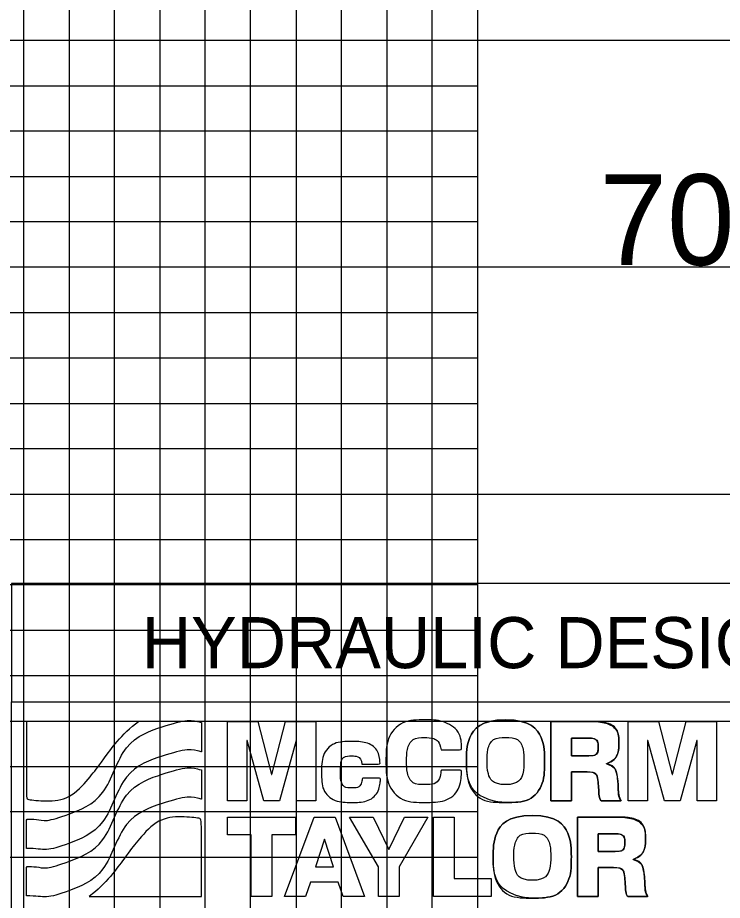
# Model space of a CAD drawing. Extents: x 1524869 to 1526553, y 501099 to 502199.
# Drawn here: x 1526435.4 to 1526513, y 501178.8 to 501276.1 of the extents above; entities that cross this region are included whole.
import ezdxf

# ---------------------------------------------------------------- set-up
doc = ezdxf.new("R2010")
doc.units = 0
for name, color, linetype in [('Exist Vertical Profile Vertical Axis Label', 7, 'Continuous'), ('Prop Grid Mask', 7, 'Continuous'), ('Prop Horizontal Alignment Curve and Spiral Data', 7, 'Continuous'), ('Sheet Layout Profile Border Port 1', 7, 'Continuous'), ('Sheet Profile Grid Major CELL', 7, 'Continuous'), ('Sheet Profile Grid Middle CELL', 7, 'Continuous'), ('Sheet Profile Grid Minor CELL', 7, 'Continuous')]:
    doc.layers.add(name, color=color, linetype=linetype)

msp = doc.modelspace()

# ---------------------------------------------------------------- linework, layer by layer
at = {"layer": 'Prop Grid Mask'}
for points in [[(1526434.749, 501200.682), (1526536.08, 501200.682), (1526536.08, 501213.727), (1526434.749, 501213.727)], [(1526434.749, 501200.682), (1526536.08, 501200.682), (1526536.08, 501148.562), (1526434.749, 501148.562)]]:
    msp.add_lwpolyline(points, close=True, dxfattribs=at)
at = {"layer": 'Prop Horizontal Alignment Curve and Spiral Data'}
for p, q in [((1526458.537, 501198.515), (1526461.888, 501198.515)), ((1526458.537, 501189.785), (1526458.537, 501198.515)), ((1526461.888, 501198.515), (1526463.392, 501192.695)), ((1526463.416, 501192.695), (1526464.92, 501198.515)), ((1526464.92, 501198.515), (1526468.27, 501198.515)), ((1526468.27, 501198.515), (1526468.27, 501189.785)), ((1526502.67, 501198.515), (1526506.021, 501198.515)), ((1526502.67, 501189.785), (1526502.67, 501198.515)), ((1526506.021, 501198.515), (1526507.524, 501192.695)), ((1526507.549, 501192.695), (1526509.052, 501198.515)), ((1526509.052, 501198.515), (1526512.403, 501198.515)), ((1526512.403, 501198.515), (1526512.403, 501189.785)), ((1526460.702, 501196.412), (1526460.677, 501196.412)), ((1526460.677, 501196.412), (1526460.677, 501189.785)), ((1526462.536, 501189.785), (1526460.702, 501196.412)), ((1526466.106, 501196.412), (1526464.272, 501189.785)), ((1526466.13, 501196.412), (1526466.106, 501196.412)), ((1526466.13, 501189.785), (1526466.13, 501196.412)), ((1526504.835, 501196.412), (1526504.81, 501196.412)), ((1526504.81, 501196.412), (1526504.81, 501189.785)), ((1526506.668, 501189.785), (1526504.835, 501196.412)), ((1526510.238, 501196.412), (1526508.404, 501189.785)), ((1526510.263, 501196.412), (1526510.238, 501196.412)), ((1526510.263, 501189.785), (1526510.263, 501196.412)), ((1526500.273, 501193.868), (1526500.273, 501193.844)), ((1526463.392, 501192.695), (1526463.416, 501192.695)), ((1526507.524, 501192.695), (1526507.549, 501192.695)), ((1526460.677, 501189.785), (1526458.537, 501189.785)), ((1526464.272, 501189.785), (1526462.536, 501189.785)), ((1526468.27, 501189.785), (1526466.13, 501189.785)), ((1526501.911, 501189.785), (1526499.662, 501189.785)), ((1526504.81, 501189.785), (1526502.67, 501189.785)), ((1526508.404, 501189.785), (1526506.668, 501189.785)), ((1526512.403, 501189.785), (1526510.263, 501189.785)), ((1526458.537, 501186.021), (1526458.537, 501187.977)), ((1526458.537, 501187.977), (1526466.02, 501187.977)), ((1526464.799, 501179.247), (1526468.064, 501187.977)), ((1526466.02, 501187.977), (1526466.02, 501186.021)), ((1526468.064, 501187.977), (1526470.374, 501187.977)), ((1526470.374, 501187.977), (1526473.639, 501179.247)), ((1526475.16, 501182.499), (1526471.981, 501187.977)), ((1526471.981, 501187.977), (1526474.561, 501187.977)), ((1526474.561, 501187.977), (1526476.297, 501184.431)), ((1526476.297, 501184.431), (1526478.034, 501187.977)), ((1526480.613, 501187.977), (1526477.435, 501182.499)), ((1526478.034, 501187.977), (1526480.613, 501187.977)), ((1526481.214, 501187.977), (1526483.488, 501187.977)), ((1526481.214, 501179.247), (1526481.214, 501187.977)), ((1526483.488, 501187.977), (1526483.488, 501181.203)), ((1526461.142, 501186.021), (1526458.537, 501186.021)), ((1526461.142, 501179.247), (1526461.142, 501186.021)), ((1526466.02, 501186.021), (1526463.416, 501186.021)), ((1526463.416, 501186.021), (1526463.416, 501179.247)), ((1526469.201, 501185.556), (1526468.21, 501182.499)), ((1526469.225, 501185.556), (1526469.201, 501185.556)), ((1526470.191, 501182.499), (1526469.225, 501185.556)), ((1526503.207, 501183.33), (1526503.207, 501183.306)), ((1526468.21, 501182.499), (1526470.191, 501182.499)), ((1526475.16, 501179.247), (1526475.16, 501182.499)), ((1526477.435, 501182.499), (1526477.435, 501179.247)), ((1526483.488, 501181.203), (1526487.56, 501181.203)), ((1526487.56, 501181.203), (1526487.56, 501179.247)), ((1526467.685, 501180.811), (1526467.134, 501179.247)), ((1526470.729, 501180.811), (1526467.685, 501180.811)), ((1526471.267, 501179.247), (1526470.729, 501180.811)), ((1526463.416, 501179.247), (1526461.142, 501179.247)), ((1526467.134, 501179.247), (1526464.799, 501179.247)), ((1526473.639, 501179.247), (1526471.267, 501179.247)), ((1526477.435, 501179.247), (1526475.16, 501179.247)), ((1526487.56, 501179.247), (1526481.214, 501179.247)), ((1526504.845, 501179.247), (1526502.596, 501179.247))]:
    msp.add_line(p, q, dxfattribs=at)
for points in [[(1526458.537, 501198.515), (1526461.888, 501198.515), (1526463.392, 501192.695), (1526463.416, 501192.695), (1526464.92, 501198.515), (1526468.27, 501198.515), (1526468.27, 501189.785), (1526466.13, 501189.785), (1526466.13, 501196.412), (1526466.106, 501196.412), (1526464.272, 501189.785), (1526462.536, 501189.785), (1526460.702, 501196.412), (1526460.677, 501196.412), (1526460.677, 501189.785), (1526458.537, 501189.785), (1526458.537, 501198.515)], [(1526498.133, 501192.964), (1526496.409, 501192.964), (1526496.409, 501189.785), (1526494.135, 501189.785), (1526494.135, 501198.515), (1526498.586, 501198.515)], [(1526502.67, 501198.515), (1526506.021, 501198.515), (1526507.524, 501192.695), (1526507.549, 501192.695), (1526509.052, 501198.515), (1526512.403, 501198.515), (1526512.403, 501189.785), (1526510.263, 501189.785), (1526510.263, 501196.412), (1526510.238, 501196.412), (1526508.404, 501189.785), (1526506.668, 501189.785), (1526504.835, 501196.412), (1526504.81, 501196.412), (1526504.81, 501189.785), (1526502.67, 501189.785), (1526502.67, 501198.515)], [(1526498.219, 501196.693), (1526496.409, 501196.693), (1526496.409, 501194.724), (1526498.317, 501194.724)], [(1526466.02, 501186.021), (1526463.416, 501186.021), (1526463.416, 501179.247), (1526461.142, 501179.247), (1526461.142, 501186.021), (1526458.537, 501186.021), (1526458.537, 501187.977), (1526466.02, 501187.977), (1526466.02, 501186.021)], [(1526468.064, 501187.977), (1526470.374, 501187.977), (1526473.639, 501179.247), (1526471.267, 501179.247), (1526470.729, 501180.811), (1526467.685, 501180.811), (1526467.134, 501179.247), (1526464.799, 501179.247), (1526468.064, 501187.977)], [(1526477.435, 501182.499), (1526477.435, 501179.247), (1526475.16, 501179.247), (1526475.16, 501182.499), (1526471.981, 501187.977), (1526474.561, 501187.977), (1526476.297, 501184.431), (1526478.034, 501187.977), (1526480.613, 501187.977), (1526477.435, 501182.499)], [(1526481.214, 501187.977), (1526483.488, 501187.977), (1526483.488, 501181.203), (1526487.56, 501181.203), (1526487.56, 501179.247), (1526481.214, 501179.247), (1526481.214, 501187.977)], [(1526501.067, 501182.426), (1526499.343, 501182.426), (1526499.343, 501179.247), (1526497.069, 501179.247), (1526497.069, 501187.977), (1526501.519, 501187.977)], [(1526501.153, 501186.155), (1526499.343, 501186.155), (1526499.343, 501184.187), (1526501.251, 501184.187)], [(1526468.21, 501182.499), (1526470.191, 501182.499), (1526469.225, 501185.556), (1526469.201, 501185.556), (1526468.21, 501182.499)]]:
    msp.add_lwpolyline(points, dxfattribs=at)
for points in [[(1526436.372, 501184.534), (1526437.494, 501184.534), (1526438.503, 501184.236), (1526440.63, 501184.902), (1526445.328, 501186.711), (1526446.854, 501193.206), (1526451.716, 501194.85), (1526454.277, 501195.577), (1526455.654, 501195.168), (1526455.654, 501195.168), (1526455.654, 501195.168), (1526455.654, 501198.398), (1526455.654, 501198.398), (1526455.654, 501198.398), (1526454.277, 501198.807), (1526451.716, 501198.08), (1526446.854, 501196.436), (1526445.328, 501189.94), (1526440.63, 501188.132), (1526438.503, 501187.466), (1526437.494, 501187.764), (1526436.372, 501187.764), (1526436.372, 501187.764), (1526436.372, 501184.534), (1526436.372, 501184.534)], [(1526436.372, 501184.534), (1526437.494, 501184.534), (1526438.503, 501184.236), (1526440.63, 501184.902), (1526445.328, 501186.711), (1526446.854, 501193.206), (1526451.716, 501194.85), (1526454.277, 501195.577), (1526455.654, 501195.168), (1526455.654, 501195.168), (1526455.654, 501195.168), (1526455.654, 501198.398), (1526455.654, 501198.398), (1526455.654, 501198.398), (1526454.277, 501198.807), (1526451.716, 501198.08), (1526446.854, 501196.436), (1526445.328, 501189.94), (1526440.63, 501188.132), (1526438.503, 501187.466), (1526437.494, 501187.764), (1526436.372, 501187.764), (1526436.372, 501187.764), (1526436.372, 501184.534), (1526436.372, 501184.534)], [(1526482.052, 501195.397), (1526481.929, 501196.277), (1526481.245, 501196.742), (1526480.291, 501196.742), (1526478.824, 501196.742), (1526478.261, 501195.446), (1526478.261, 501194.15), (1526478.261, 501192.854), (1526478.824, 501191.558), (1526480.291, 501191.558), (1526481.355, 501191.558), (1526481.966, 501192.169), (1526482.052, 501193.171), (1526482.052, 501193.171), (1526484.326, 501193.171), (1526484.326, 501193.171), (1526484.203, 501190.921), (1526482.553, 501189.602), (1526480.339, 501189.602), (1526477.699, 501189.602), (1526475.987, 501191.619), (1526475.987, 501194.15), (1526475.987, 501196.68), (1526477.699, 501198.698), (1526480.339, 501198.698), (1526482.223, 501198.698), (1526484.265, 501197.5), (1526484.326, 501195.397), (1526484.326, 501195.397), (1526482.052, 501195.397), (1526482.052, 501195.397)], [(1526482.052, 501195.397), (1526481.929, 501196.277), (1526481.245, 501196.742), (1526480.291, 501196.742), (1526478.824, 501196.742), (1526478.261, 501195.446), (1526478.261, 501194.15), (1526478.261, 501192.854), (1526478.824, 501191.558), (1526480.291, 501191.558), (1526481.355, 501191.558), (1526481.966, 501192.169), (1526482.052, 501193.171), (1526482.052, 501193.171), (1526484.326, 501193.171), (1526484.326, 501193.171), (1526484.203, 501190.921), (1526482.553, 501189.602), (1526480.339, 501189.602), (1526477.699, 501189.602), (1526475.987, 501191.619), (1526475.987, 501194.15), (1526475.987, 501196.68), (1526477.699, 501198.698), (1526480.339, 501198.698), (1526482.223, 501198.698), (1526484.265, 501197.5), (1526484.326, 501195.397), (1526484.326, 501195.397), (1526482.052, 501195.397), (1526482.052, 501195.397)], [(1526488.094, 501189.711), (1526486.008, 501190.164), (1526484.852, 501191.965), (1526484.852, 501194.15), (1526484.852, 501196.68), (1526486.404, 501198.698), (1526489.156, 501198.698)], [(1526489.156, 501198.698), (1526491.907, 501198.698), (1526493.46, 501196.68), (1526493.46, 501194.15), (1526493.46, 501191.619), (1526491.907, 501189.602), (1526489.156, 501189.602), (1526486.404, 501189.602), (1526484.852, 501191.619), (1526484.852, 501194.15), (1526484.852, 501196.68), (1526486.404, 501198.698), (1526489.156, 501198.698)], [(1526489.156, 501198.698), (1526491.907, 501198.698), (1526493.46, 501196.68), (1526493.46, 501194.15), (1526493.46, 501191.619), (1526491.907, 501189.602), (1526489.156, 501189.602), (1526488.779, 501189.602), (1526488.425, 501189.639), (1526488.094, 501189.711)], [(1526448.729, 501198.528), (1526446.824, 501197.124), (1526444.486, 501193.737), (1526443.601, 501192.679), (1526441.412, 501190.065), (1526438.919, 501189.64), (1526436.372, 501189.944), (1526436.372, 501189.944), (1526436.372, 501198.528), (1526436.372, 501198.528), (1526436.372, 501198.528), (1526448.729, 501198.528), (1526448.729, 501198.528)], [(1526448.729, 501198.528), (1526446.824, 501197.124), (1526444.486, 501193.737), (1526443.601, 501192.679), (1526441.412, 501190.065), (1526438.919, 501189.64), (1526436.372, 501189.944), (1526436.372, 501189.944), (1526436.372, 501198.528), (1526436.372, 501198.528), (1526436.372, 501198.528), (1526448.729, 501198.528), (1526448.729, 501198.528)], [(1526494.135, 501198.515), (1526494.135, 501198.515), (1526498.586, 501198.515), (1526498.586, 501198.515), (1526500.127, 501198.515), (1526501.642, 501197.818), (1526501.642, 501196.057), (1526501.642, 501195.116), (1526501.191, 501194.223), (1526500.273, 501193.868), (1526500.273, 501193.868), (1526500.273, 501193.844), (1526500.273, 501193.844), (1526501.202, 501193.624), (1526501.471, 501192.585), (1526501.545, 501191.753), (1526501.57, 501191.386), (1526501.606, 501190.103), (1526501.911, 501189.785), (1526501.911, 501189.785), (1526499.662, 501189.785), (1526499.662, 501189.785), (1526499.466, 501190.078), (1526499.429, 501190.934), (1526499.405, 501191.178), (1526499.344, 501192.059), (1526499.197, 501192.964), (1526498.133, 501192.964), (1526498.133, 501192.964), (1526496.409, 501192.964), (1526496.409, 501192.964), (1526496.409, 501192.964), (1526496.409, 501189.785), (1526496.409, 501189.785), (1526496.409, 501189.785), (1526494.135, 501189.785), (1526494.135, 501189.785), (1526494.135, 501189.785), (1526494.135, 501198.515), (1526494.135, 501198.515)], [(1526498.586, 501198.515), (1526500.127, 501198.515), (1526501.642, 501197.818), (1526501.642, 501196.057), (1526501.642, 501195.116), (1526501.191, 501194.223), (1526500.273, 501193.868)], [(1526489.156, 501191.558), (1526490.623, 501191.558), (1526491.186, 501192.854), (1526491.186, 501194.15), (1526491.186, 501195.446), (1526490.623, 501196.742), (1526489.156, 501196.742), (1526487.688, 501196.742), (1526487.126, 501195.446), (1526487.126, 501194.15), (1526487.126, 501192.854), (1526487.688, 501191.558), (1526489.156, 501191.558)], [(1526489.156, 501191.558), (1526490.623, 501191.558), (1526491.186, 501192.854), (1526491.186, 501194.15), (1526491.186, 501195.446), (1526490.623, 501196.742), (1526489.156, 501196.742), (1526487.688, 501196.742), (1526487.126, 501195.446), (1526487.126, 501194.15), (1526487.126, 501192.854), (1526487.688, 501191.558), (1526489.156, 501191.558)], [(1526496.409, 501194.724), (1526496.409, 501194.724), (1526498.317, 501194.724), (1526498.317, 501194.724), (1526499.001, 501194.724), (1526499.368, 501195.091), (1526499.368, 501195.751), (1526499.368, 501196.4), (1526498.855, 501196.693), (1526498.219, 501196.693), (1526498.219, 501196.693), (1526496.409, 501196.693), (1526496.409, 501196.693), (1526496.409, 501196.693), (1526496.409, 501194.724), (1526496.409, 501194.724)], [(1526498.317, 501194.724), (1526499.001, 501194.724), (1526499.368, 501195.091), (1526499.368, 501195.751), (1526499.368, 501196.4), (1526498.855, 501196.693), (1526498.219, 501196.693)], [(1526473.33, 501193.807), (1526473.318, 501194.345), (1526472.841, 501194.724), (1526472.315, 501194.724), (1526471.154, 501194.724), (1526470.97, 501193.734), (1526470.97, 501192.854), (1526470.97, 501192.034), (1526471.324, 501191.191), (1526472.205, 501191.191), (1526472.926, 501191.191), (1526473.293, 501191.606), (1526473.391, 501192.279), (1526473.391, 501192.279), (1526475.408, 501192.279), (1526475.408, 501192.279), (1526475.225, 501190.579), (1526473.905, 501189.602), (1526472.217, 501189.602), (1526470.31, 501189.602), (1526468.891, 501190.909), (1526468.891, 501192.854), (1526468.891, 501194.871), (1526470.175, 501196.314), (1526472.217, 501196.314), (1526473.794, 501196.314), (1526475.201, 501195.483), (1526475.347, 501193.807), (1526475.347, 501193.807), (1526473.33, 501193.807), (1526473.33, 501193.807)], [(1526473.33, 501193.807), (1526473.318, 501194.345), (1526472.841, 501194.724), (1526472.315, 501194.724), (1526471.154, 501194.724), (1526470.97, 501193.734), (1526470.97, 501192.854), (1526470.97, 501192.034), (1526471.324, 501191.191), (1526472.205, 501191.191), (1526472.926, 501191.191), (1526473.293, 501191.606), (1526473.391, 501192.279), (1526473.391, 501192.279), (1526475.408, 501192.279), (1526475.408, 501192.279), (1526475.225, 501190.579), (1526473.905, 501189.602), (1526472.217, 501189.602), (1526470.31, 501189.602), (1526468.891, 501190.909), (1526468.891, 501192.854), (1526468.891, 501194.871), (1526470.175, 501196.314), (1526472.217, 501196.314), (1526473.794, 501196.314), (1526475.201, 501195.483), (1526475.347, 501193.807), (1526475.347, 501193.807), (1526473.33, 501193.807), (1526473.33, 501193.807)], [(1526500.273, 501193.844), (1526501.202, 501193.624), (1526501.471, 501192.585), (1526501.545, 501191.753), (1526501.57, 501191.386), (1526501.606, 501190.103), (1526501.911, 501189.785)], [(1526436.372, 501179.313), (1526437.494, 501179.313), (1526438.503, 501179.014), (1526440.63, 501179.681), (1526445.328, 501181.489), (1526446.854, 501187.985), (1526451.716, 501189.628), (1526454.277, 501190.356), (1526455.654, 501189.947), (1526455.654, 501189.947), (1526455.654, 501189.947), (1526455.654, 501193.177), (1526455.654, 501193.177), (1526455.654, 501193.177), (1526454.277, 501193.586), (1526451.716, 501192.858), (1526446.854, 501191.215), (1526445.328, 501184.718), (1526440.63, 501182.91), (1526438.503, 501182.244), (1526437.494, 501182.543), (1526436.372, 501182.543), (1526436.372, 501182.543), (1526436.372, 501179.313), (1526436.372, 501179.313)], [(1526436.372, 501179.313), (1526437.494, 501179.313), (1526438.503, 501179.014), (1526440.63, 501179.681), (1526445.328, 501181.489), (1526446.854, 501187.985), (1526451.716, 501189.628), (1526454.277, 501190.356), (1526455.654, 501189.947), (1526455.654, 501189.947), (1526455.654, 501189.947), (1526455.654, 501193.177), (1526455.654, 501193.177), (1526455.654, 501193.177), (1526454.277, 501193.586), (1526451.716, 501192.858), (1526446.854, 501191.215), (1526445.328, 501184.718), (1526440.63, 501182.91), (1526438.503, 501182.244), (1526437.494, 501182.543), (1526436.372, 501182.543), (1526436.372, 501182.543), (1526436.372, 501179.313), (1526436.372, 501179.313)], [(1526499.662, 501189.785), (1526499.466, 501190.078), (1526499.429, 501190.934), (1526499.405, 501191.178), (1526499.344, 501192.059), (1526499.197, 501192.964), (1526498.133, 501192.964)], [(1526443.296, 501179.246), (1526445.201, 501180.65), (1526447.538, 501184.038), (1526448.424, 501185.095), (1526450.612, 501187.71), (1526453.105, 501188.134), (1526455.653, 501187.83), (1526455.653, 501187.83), (1526455.653, 501179.246), (1526455.653, 501179.246), (1526455.653, 501179.246), (1526443.296, 501179.246), (1526443.296, 501179.246)], [(1526443.296, 501179.246), (1526445.201, 501180.65), (1526447.538, 501184.038), (1526448.424, 501185.095), (1526450.612, 501187.71), (1526453.105, 501188.134), (1526455.653, 501187.83), (1526455.653, 501187.83), (1526455.653, 501179.246), (1526455.653, 501179.246), (1526455.653, 501179.246), (1526443.296, 501179.246), (1526443.296, 501179.246)], [(1526491.039, 501179.173), (1526488.954, 501179.625), (1526487.797, 501181.427), (1526487.797, 501183.612), (1526487.797, 501186.143), (1526489.35, 501188.16), (1526492.101, 501188.16)], [(1526492.101, 501188.16), (1526494.852, 501188.16), (1526496.405, 501186.143), (1526496.405, 501183.612), (1526496.405, 501181.08), (1526494.852, 501179.063), (1526492.101, 501179.063), (1526489.35, 501179.063), (1526487.797, 501181.08), (1526487.797, 501183.612), (1526487.797, 501186.143), (1526489.35, 501188.16), (1526492.101, 501188.16)], [(1526492.101, 501188.16), (1526494.852, 501188.16), (1526496.405, 501186.143), (1526496.405, 501183.612), (1526496.405, 501181.08), (1526494.852, 501179.063), (1526492.101, 501179.063), (1526491.725, 501179.063), (1526491.37, 501179.101), (1526491.039, 501179.173)], [(1526497.069, 501187.977), (1526497.069, 501187.977), (1526501.519, 501187.977), (1526501.519, 501187.977), (1526503.06, 501187.977), (1526504.576, 501187.28), (1526504.576, 501185.519), (1526504.576, 501184.578), (1526504.124, 501183.685), (1526503.207, 501183.33), (1526503.207, 501183.33), (1526503.207, 501183.306), (1526503.207, 501183.306), (1526504.136, 501183.086), (1526504.405, 501182.047), (1526504.478, 501181.215), (1526504.503, 501180.848), (1526504.54, 501179.565), (1526504.845, 501179.247), (1526504.845, 501179.247), (1526502.596, 501179.247), (1526502.596, 501179.247), (1526502.4, 501179.54), (1526502.363, 501180.396), (1526502.339, 501180.641), (1526502.278, 501181.521), (1526502.131, 501182.426), (1526501.067, 501182.426), (1526501.067, 501182.426), (1526499.343, 501182.426), (1526499.343, 501182.426), (1526499.343, 501182.426), (1526499.343, 501179.247), (1526499.343, 501179.247), (1526499.343, 501179.247), (1526497.069, 501179.247), (1526497.069, 501179.247), (1526497.069, 501179.247), (1526497.069, 501187.977), (1526497.069, 501187.977)], [(1526501.519, 501187.977), (1526503.06, 501187.977), (1526504.576, 501187.28), (1526504.576, 501185.519), (1526504.576, 501184.578), (1526504.124, 501183.685), (1526503.207, 501183.33)], [(1526492.101, 501181.02), (1526493.569, 501181.02), (1526494.131, 501182.316), (1526494.131, 501183.612), (1526494.131, 501184.908), (1526493.569, 501186.204), (1526492.101, 501186.204), (1526490.634, 501186.204), (1526490.072, 501184.908), (1526490.072, 501183.612), (1526490.072, 501182.316), (1526490.634, 501181.02), (1526492.101, 501181.02)], [(1526492.101, 501181.02), (1526493.569, 501181.02), (1526494.131, 501182.316), (1526494.131, 501183.612), (1526494.131, 501184.908), (1526493.569, 501186.204), (1526492.101, 501186.204), (1526490.634, 501186.204), (1526490.072, 501184.908), (1526490.072, 501183.612), (1526490.072, 501182.316), (1526490.634, 501181.02), (1526492.101, 501181.02)], [(1526499.343, 501184.187), (1526499.343, 501184.187), (1526501.251, 501184.187), (1526501.251, 501184.187), (1526501.935, 501184.187), (1526502.302, 501184.553), (1526502.302, 501185.213), (1526502.302, 501185.862), (1526501.789, 501186.155), (1526501.153, 501186.155), (1526501.153, 501186.155), (1526499.343, 501186.155), (1526499.343, 501186.155), (1526499.343, 501186.155), (1526499.343, 501184.187), (1526499.343, 501184.187)], [(1526501.251, 501184.187), (1526501.935, 501184.187), (1526502.302, 501184.553), (1526502.302, 501185.213), (1526502.302, 501185.862), (1526501.789, 501186.155), (1526501.153, 501186.155)], [(1526503.207, 501183.306), (1526504.136, 501183.086), (1526504.405, 501182.047), (1526504.478, 501181.215), (1526504.503, 501180.848), (1526504.54, 501179.565), (1526504.845, 501179.247)], [(1526502.596, 501179.247), (1526502.4, 501179.54), (1526502.363, 501180.396), (1526502.339, 501180.641), (1526502.278, 501181.521), (1526502.131, 501182.426), (1526501.067, 501182.426)]]:
    msp.add_open_spline(points, degree=3, dxfattribs=at)
at = {"layer": 'Sheet Layout Profile Border Port 1'}
msp.add_lwpolyline([(1525536.08, 501648.562), (1526486.08, 501648.562), (1526486.08, 501148.562), (1525536.08, 501148.562)], close=True, dxfattribs=at)
at = {"layer": 'Sheet Profile Grid Major CELL'}
for points in [[(1525986.08, 501148.562), (1526036.08, 501148.562), (1526036.08, 501648.562), (1526086.08, 501648.562), (1526086.08, 501148.562), (1526136.08, 501148.562), (1526136.08, 501648.562), (1526186.08, 501648.562), (1526186.08, 501148.562), (1526236.08, 501148.562), (1526236.08, 501648.562), (1526286.08, 501648.562), (1526286.08, 501148.562), (1526336.08, 501148.562), (1526336.08, 501648.562), (1526386.08, 501648.562), (1526386.08, 501148.562), (1526436.08, 501148.562), (1526436.08, 501148.562), (1526436.08, 501648.562), (1526486.08, 501648.562), (1526486.08, 501148.562)], [(1526536.08, 501248.562), (1525036.08, 501248.562), (1525036.08, 501248.562), (1525036.08, 501198.562), (1526536.08, 501198.562)]]:
    msp.add_lwpolyline(points, dxfattribs=at)
at = {"layer": 'Sheet Profile Grid Middle CELL'}
for points in [[(1526011.08, 501148.562), (1526061.08, 501148.562), (1526061.08, 501648.562), (1526111.08, 501648.562), (1526111.08, 501148.562), (1526161.08, 501148.562), (1526161.08, 501648.562), (1526211.08, 501648.562), (1526211.08, 501148.562), (1526261.08, 501148.562), (1526261.08, 501648.562), (1526311.08, 501648.562), (1526311.08, 501148.562), (1526361.08, 501148.562), (1526361.08, 501648.562), (1526411.08, 501648.562), (1526411.08, 501148.562), (1526461.08, 501148.562), (1526461.08, 501648.562)], [(1526536.08, 501273.562), (1525036.08, 501273.562), (1525036.08, 501223.562), (1526536.08, 501223.562)]]:
    msp.add_lwpolyline(points, dxfattribs=at)
at = {"layer": 'Sheet Profile Grid Minor CELL'}
for p, q in [((1526036.08, 501268.562), (1526486.08, 501268.562)), ((1526486.08, 501263.562), (1526036.08, 501263.562)), ((1526036.08, 501258.562), (1526486.08, 501258.562)), ((1526486.08, 501253.562), (1526036.08, 501253.562)), ((1526036.08, 501243.562), (1526486.08, 501243.562)), ((1526486.08, 501238.562), (1526036.08, 501238.562)), ((1526036.08, 501233.562), (1526486.08, 501233.562)), ((1526486.08, 501228.562), (1526036.08, 501228.562)), ((1526036.08, 501218.562), (1526486.08, 501218.562)), ((1526486.08, 501213.562), (1526036.08, 501213.562)), ((1526036.08, 501208.562), (1526486.08, 501208.562)), ((1526486.08, 501203.562), (1526036.08, 501203.562)), ((1526036.08, 501193.562), (1526486.08, 501193.562)), ((1526486.08, 501188.562), (1526036.08, 501188.562)), ((1526036.08, 501183.562), (1526486.08, 501183.562))]:
    msp.add_line(p, q, dxfattribs=at)
for points in [[(1526441.08, 501648.562), (1526441.08, 501148.562), (1526446.08, 501148.562), (1526446.08, 501648.562)], [(1526451.08, 501648.562), (1526451.08, 501148.562), (1526456.08, 501148.562), (1526456.08, 501648.562)], [(1526466.08, 501648.562), (1526466.08, 501148.562), (1526471.08, 501148.562), (1526471.08, 501648.562)], [(1526476.08, 501648.562), (1526476.08, 501148.562), (1526481.08, 501148.562), (1526481.08, 501648.562)]]:
    msp.add_lwpolyline(points, dxfattribs=at)

# ---------------------------------------------------------------- texts
at = {"layer": 'Exist Vertical Profile Vertical Axis Label'}
msp.add_text('700', height=10, dxfattribs=at).set_placement((1526499.512, 501248.812))
at = {"layer": 'Prop Horizontal Alignment Curve and Spiral Data'}
msp.add_text('HYDRAULIC DESIGN', height=5.625, rotation=360, dxfattribs=at).set_placement((1526449.092, 501204.392))

doc.saveas('drawing.dxf')
